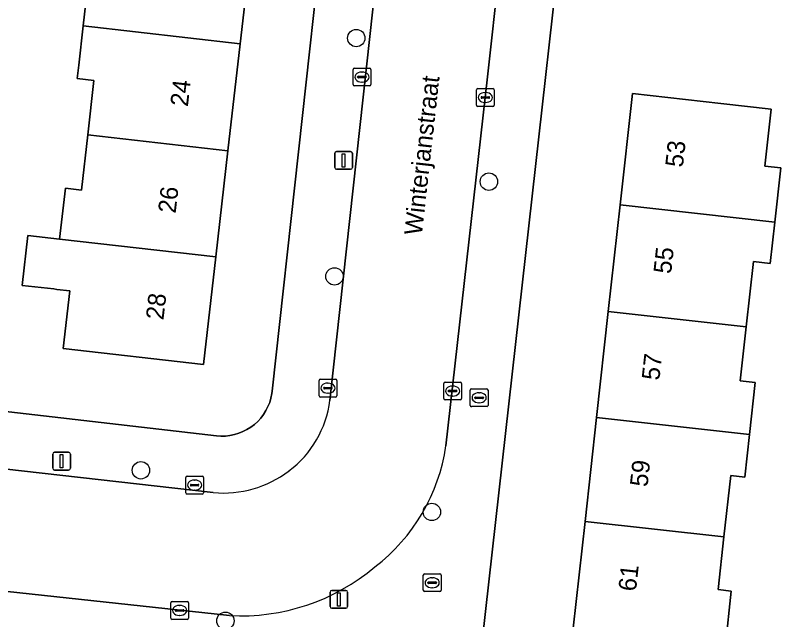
# Model space of a CAD drawing. Extents: x 162026 to 163502, y 387295 to 388169.
# Drawn here: x 162399.19 to 162442.26, y 387674.72 to 387708.7 of the extents above; entities that cross this region are included whole.
import ezdxf

# ---------------------------------------------------------------- set-up
doc = ezdxf.new("R2010")
doc.units = 0
for name, color, linetype in [('IMGEO_Boom', 7, 'Continuous'), ('IMGEO_Brandkraan', 7, 'Continuous'), ('IMGEO_Erf', 7, 'Continuous'), ('IMGEO_Kolk', 7, 'Continuous'), ('IMGEO_Lichtmast', 7, 'Continuous'), ('IMGEO_Openbare_ruimte_label', 7, 'Continuous'), ('IMGEO_Pand', 7, 'Continuous'), ('IMGEO_Pand_nummerreeks', 7, 'Continuous'), ('IMGEO_Rijbaan_lokaal_open', 7, 'Continuous'), ('IMGEO_Rioolput', 7, 'Continuous'), ('IMGEO_Voetpad_open', 7, 'Continuous')]:
    doc.layers.add(name, color=color, linetype=linetype)

msp = doc.modelspace()

# ---------------------------------------------------------------- linework, layer by layer
at = {"layer": 'IMGEO_Boom'}
for centre in [(162418.373, 387707.415), (162425.838, 387699.344), (162417.151, 387694.018), (162406.254, 387683.117), (162422.629, 387680.775), (162411.013, 387674.656)]:
    msp.add_circle(centre, 0.489, dxfattribs=at)
at = {"layer": 'IMGEO_Brandkraan'}
for p, q in [((162424.79, 387686.769), (162424.79, 387687.621)), ((162424.865, 387687.695), (162425.717, 387687.695)), ((162425.278, 387687.475), (162425.303, 387687.475)), ((162425.791, 387687.621), (162425.791, 387686.769)), ((162425.049, 387687.189), (162425.049, 387687.201)), ((162425.487, 387687.152), (162425.089, 387687.152)), ((162425.092, 387687.238), (162425.49, 387687.238)), ((162425.301, 387686.915), (162425.276, 387686.915)), ((162425.533, 387687.201), (162425.533, 387687.189)), ((162425.717, 387686.695), (162424.865, 387686.695))]:
    msp.add_line(p, q, dxfattribs=at)
for points in [[(162424.79, 387686.769), (162424.79, 387687.621)], [(162424.865, 387687.695), (162425.717, 387687.695)], [(162425.791, 387687.621), (162425.791, 387686.769)], [(162425.717, 387686.695), (162424.865, 387686.695)]]:
    msp.add_lwpolyline(points, dxfattribs=at)
for centre, radius, start, end in [((162424.867, 387687.619), 0.0765, 91.552, 178.448), ((162424.867, 387687.619), 0.0765, 91.552, 178.448), ((162425.715, 387687.619), 0.0765, 1.552, 88.448), ((162425.715, 387687.619), 0.0765, 1.552, 88.448), ((162425.089, 387687.198), 0.0403, 85.8775, 175.7526), ((162425.086, 387687.188), 0.0366, 178.938, 274.7102), ((162425.49, 387687.195), 0.043, 264.8664, 352.4533), ((162425.494, 387687.2), 0.0386, 1.7309, 96.639), ((162424.867, 387686.771), 0.0765, 181.552, 268.448), ((162424.867, 387686.771), 0.0765, 181.552, 268.448), ((162425.715, 387686.771), 0.0765, 271.552, 358.448), ((162425.715, 387686.771), 0.0765, 271.552, 358.448)]:
    msp.add_arc(centre, radius, start, end, dxfattribs=at)
for centre, major_axis, ratio, start_param, end_param in [((162425.277, 387687.195), (-0.387, 0.002), 0.722429, 4.712389, 7.853982), ((162425.302, 387687.195), (-0.39, 0.002), 0.717154, 1.570796, 4.712389)]:
    msp.add_ellipse(centre, major_axis=major_axis, ratio=ratio, start_param=start_param, end_param=end_param, dxfattribs=at)
at = {"layer": 'IMGEO_Erf'}
for points in [[(162433.651, 387750.442), (162432.585, 387742.149), (162433.168, 387742.074), (162425.088, 387670.179)], [(162390.537, 387687.351), (162410.507, 387685.056), (162410.761, 387685.039), (162411.015, 387685.045), (162411.268, 387685.074), (162411.517, 387685.125), (162411.761, 387685.198), (162411.997, 387685.292), (162412.223, 387685.408), (162412.439, 387685.543), (162412.641, 387685.697), (162412.829, 387685.868), (162413.001, 387686.055), (162413.156, 387686.257), (162413.292, 387686.472), (162413.408, 387686.699), (162413.503, 387686.934), (162413.577, 387687.178), (162413.629, 387687.427), (162413.649, 387687.57), (162418.095, 387727.958)], [(162412.529, 387713.102), (162411.84, 387707.09), (162411.151, 387701.077), (162410.467, 387695.109), (162409.775, 387689.069), (162401.884, 387689.973), (162402.255, 387693.207), (162401.523, 387693.291), (162401.357, 387693.31), (162399.573, 387693.515), (162399.894, 387696.322), (162401.679, 387696.117), (162402.007, 387698.976), (162402.91, 387698.873), (162403.266, 387701.981), (162403.616, 387705.035), (162402.67, 387705.144), (162402.757, 387705.902), (162403.009, 387708.103), (162403.313, 387710.755)], [(162430.585, 387674.243), (162431.25, 387680.243), (162431.898, 387686.091), (162432.557, 387692.036), (162433.221, 387698.036), (162433.915, 387704.295), (162438.885, 387703.744), (162441.722, 387703.429), (162441.366, 387700.218), (162442.261, 387700.119), (162441.924, 387697.072), (162441.666, 387694.743), (162440.726, 387694.847), (162440.319, 387691.175), (162439.983, 387688.144), (162440.831, 387688.05), (162440.508, 387685.137), (162440.243, 387682.739), (162439.449, 387682.827), (162439.067, 387679.377), (162438.738, 387676.41), (162439.482, 387676.327), (162439.146, 387673.294)]]:
    msp.add_lwpolyline(points, dxfattribs=at)
at = {"layer": 'IMGEO_Kolk'}
for p, q in [((162418.195, 387704.799), (162418.195, 387705.651)), ((162418.27, 387705.725), (162419.122, 387705.725)), ((162418.683, 387705.505), (162418.708, 387705.505)), ((162419.196, 387705.651), (162419.196, 387704.799)), ((162418.454, 387705.219), (162418.454, 387705.231)), ((162418.892, 387705.182), (162418.494, 387705.182)), ((162418.497, 387705.268), (162418.895, 387705.268)), ((162418.938, 387705.231), (162418.938, 387705.219)), ((162419.122, 387704.725), (162418.27, 387704.725)), ((162418.706, 387704.945), (162418.681, 387704.945)), ((162425.214, 387704.575), (162426.066, 387704.575)), ((162425.139, 387703.649), (162425.139, 387704.501)), ((162425.627, 387704.355), (162425.652, 387704.355)), ((162426.14, 387704.501), (162426.14, 387703.649)), ((162425.398, 387704.069), (162425.398, 387704.081)), ((162425.836, 387704.032), (162425.438, 387704.032)), ((162425.441, 387704.118), (162425.839, 387704.118)), ((162425.65, 387703.795), (162425.625, 387703.795)), ((162425.882, 387704.081), (162425.882, 387704.069)), ((162426.066, 387703.575), (162425.214, 387703.575)), ((162416.357, 387688.237), (162417.209, 387688.237)), ((162416.282, 387687.311), (162416.282, 387688.163)), ((162416.584, 387687.78), (162416.982, 387687.78)), ((162416.77, 387688.017), (162416.795, 387688.017)), ((162417.283, 387688.163), (162417.283, 387687.311)), ((162423.295, 387687.146), (162423.295, 387687.998)), ((162423.37, 387688.072), (162424.222, 387688.072)), ((162423.783, 387687.852), (162423.808, 387687.852)), ((162424.296, 387687.998), (162424.296, 387687.146)), ((162416.541, 387687.731), (162416.541, 387687.743)), ((162416.979, 387687.694), (162416.581, 387687.694)), ((162416.793, 387687.457), (162416.768, 387687.457)), ((162417.025, 387687.743), (162417.025, 387687.731)), ((162423.554, 387687.566), (162423.554, 387687.578)), ((162423.992, 387687.529), (162423.594, 387687.529)), ((162423.597, 387687.615), (162423.995, 387687.615)), ((162424.038, 387687.578), (162424.038, 387687.566)), ((162417.209, 387687.237), (162416.357, 387687.237)), ((162424.222, 387687.072), (162423.37, 387687.072)), ((162423.806, 387687.292), (162423.781, 387687.292)), ((162408.779, 387681.859), (162408.779, 387682.711)), ((162408.854, 387682.785), (162409.706, 387682.785)), ((162409.78, 387682.711), (162409.78, 387681.859)), ((162409.038, 387682.279), (162409.038, 387682.291)), ((162409.476, 387682.242), (162409.078, 387682.242)), ((162409.081, 387682.328), (162409.479, 387682.328)), ((162409.267, 387682.565), (162409.292, 387682.565)), ((162409.522, 387682.291), (162409.522, 387682.279)), ((162409.706, 387681.785), (162408.854, 387681.785)), ((162409.29, 387682.005), (162409.265, 387682.005)), ((162408.008, 387675.739), (162408.86, 387675.739)), ((162407.933, 387674.813), (162407.933, 387675.665)), ((162408.421, 387675.519), (162408.446, 387675.519)), ((162408.934, 387675.665), (162408.934, 387674.813)), ((162408.192, 387675.233), (162408.192, 387675.245)), ((162408.63, 387675.196), (162408.232, 387675.196)), ((162408.235, 387675.282), (162408.633, 387675.282)), ((162408.444, 387674.959), (162408.419, 387674.959)), ((162408.676, 387675.245), (162408.676, 387675.233)), ((162408.86, 387674.739), (162408.008, 387674.739))]:
    msp.add_line(p, q, dxfattribs=at)
for points in [[(162418.195, 387704.799), (162418.195, 387705.651)], [(162418.27, 387705.725), (162419.122, 387705.725)], [(162419.196, 387705.651), (162419.196, 387704.799)], [(162419.122, 387704.725), (162418.27, 387704.725)], [(162425.214, 387704.575), (162426.066, 387704.575)], [(162425.139, 387703.649), (162425.139, 387704.501)], [(162426.14, 387704.501), (162426.14, 387703.649)], [(162426.066, 387703.575), (162425.214, 387703.575)], [(162416.357, 387688.237), (162417.209, 387688.237)], [(162416.282, 387687.311), (162416.282, 387688.163)], [(162417.283, 387688.163), (162417.283, 387687.311)], [(162423.295, 387687.146), (162423.295, 387687.998)], [(162423.37, 387688.072), (162424.222, 387688.072)], [(162424.296, 387687.998), (162424.296, 387687.146)], [(162417.209, 387687.237), (162416.357, 387687.237)], [(162424.222, 387687.072), (162423.37, 387687.072)], [(162408.779, 387681.859), (162408.779, 387682.711)], [(162408.854, 387682.785), (162409.706, 387682.785)], [(162409.78, 387682.711), (162409.78, 387681.859)], [(162409.706, 387681.785), (162408.854, 387681.785)], [(162408.008, 387675.739), (162408.86, 387675.739)], [(162407.933, 387674.813), (162407.933, 387675.665)], [(162408.934, 387675.665), (162408.934, 387674.813)], [(162408.86, 387674.739), (162408.008, 387674.739)]]:
    msp.add_lwpolyline(points, dxfattribs=at)
for centre, radius, start, end in [((162418.272, 387705.649), 0.0765, 91.552, 178.448), ((162418.272, 387705.649), 0.0765, 91.552, 178.448), ((162419.12, 387705.649), 0.0765, 1.552, 88.448), ((162419.12, 387705.649), 0.0765, 1.552, 88.448), ((162418.494, 387705.228), 0.0403, 85.8775, 175.7526), ((162418.491, 387705.218), 0.0366, 178.938, 274.7102), ((162418.895, 387705.225), 0.043, 264.8664, 352.4533), ((162418.899, 387705.23), 0.0386, 1.7309, 96.639), ((162418.272, 387704.801), 0.0765, 181.552, 268.448), ((162418.272, 387704.801), 0.0765, 181.552, 268.448), ((162419.12, 387704.801), 0.0765, 271.552, 358.448), ((162419.12, 387704.801), 0.0765, 271.552, 358.448), ((162425.216, 387704.499), 0.0765, 91.552, 178.448), ((162425.216, 387704.499), 0.0765, 91.552, 178.448), ((162426.064, 387704.499), 0.0765, 1.552, 88.448), ((162426.064, 387704.499), 0.0765, 1.552, 88.448), ((162425.438, 387704.078), 0.0403, 85.8775, 175.7526), ((162425.435, 387704.068), 0.0366, 178.938, 274.7102), ((162425.839, 387704.075), 0.043, 264.8664, 352.4533), ((162425.843, 387704.08), 0.0386, 1.7309, 96.639), ((162425.216, 387703.651), 0.0765, 181.552, 268.448), ((162425.216, 387703.651), 0.0765, 181.552, 268.448), ((162426.064, 387703.651), 0.0765, 271.552, 358.448), ((162426.064, 387703.651), 0.0765, 271.552, 358.448), ((162416.359, 387688.161), 0.0765, 91.552, 178.448), ((162416.359, 387688.161), 0.0765, 91.552, 178.448), ((162417.207, 387688.161), 0.0765, 1.552, 88.448), ((162417.207, 387688.161), 0.0765, 1.552, 88.448), ((162416.581, 387687.74), 0.0403, 85.8775, 175.7526), ((162416.986, 387687.742), 0.0386, 1.7309, 96.639), ((162423.372, 387687.996), 0.0765, 91.552, 178.448), ((162423.372, 387687.996), 0.0765, 91.552, 178.448), ((162424.22, 387687.996), 0.0765, 1.552, 88.448), ((162424.22, 387687.996), 0.0765, 1.552, 88.448), ((162416.578, 387687.73), 0.0366, 178.938, 274.7102), ((162416.982, 387687.737), 0.043, 264.8664, 352.4533), ((162423.594, 387687.575), 0.0403, 85.8775, 175.7526), ((162423.591, 387687.565), 0.0366, 178.938, 274.7102), ((162423.995, 387687.572), 0.043, 264.8664, 352.4533), ((162423.999, 387687.577), 0.0386, 1.7309, 96.639), ((162416.359, 387687.313), 0.0765, 181.552, 268.448), ((162416.359, 387687.313), 0.0765, 181.552, 268.448), ((162417.207, 387687.313), 0.0765, 271.552, 358.448), ((162417.207, 387687.313), 0.0765, 271.552, 358.448), ((162423.372, 387687.148), 0.0765, 181.552, 268.448), ((162423.372, 387687.148), 0.0765, 181.552, 268.448), ((162424.22, 387687.148), 0.0765, 271.552, 358.448), ((162424.22, 387687.148), 0.0765, 271.552, 358.448), ((162408.856, 387682.709), 0.0765, 91.552, 178.448), ((162408.856, 387682.709), 0.0765, 91.552, 178.448), ((162409.704, 387682.709), 0.0765, 1.552, 88.448), ((162409.704, 387682.709), 0.0765, 1.552, 88.448), ((162409.078, 387682.288), 0.0403, 85.8775, 175.7526), ((162409.075, 387682.278), 0.0366, 178.938, 274.7102), ((162409.479, 387682.285), 0.043, 264.8664, 352.4533), ((162409.483, 387682.29), 0.0386, 1.7309, 96.639), ((162408.856, 387681.861), 0.0765, 181.552, 268.448), ((162408.856, 387681.861), 0.0765, 181.552, 268.448), ((162409.704, 387681.861), 0.0765, 271.552, 358.448), ((162409.704, 387681.861), 0.0765, 271.552, 358.448), ((162408.01, 387675.663), 0.0765, 91.552, 178.448), ((162408.01, 387675.663), 0.0765, 91.552, 178.448), ((162408.858, 387675.663), 0.0765, 1.552, 88.448), ((162408.858, 387675.663), 0.0765, 1.552, 88.448), ((162408.232, 387675.242), 0.0403, 85.8775, 175.7526), ((162408.229, 387675.232), 0.0366, 178.938, 274.7102), ((162408.633, 387675.239), 0.043, 264.8664, 352.4533), ((162408.637, 387675.244), 0.0386, 1.7309, 96.639), ((162408.01, 387674.815), 0.0765, 181.552, 268.448), ((162408.01, 387674.815), 0.0765, 181.552, 268.448), ((162408.858, 387674.815), 0.0765, 271.552, 358.448), ((162408.858, 387674.815), 0.0765, 271.552, 358.448)]:
    msp.add_arc(centre, radius, start, end, dxfattribs=at)
for centre, major_axis, ratio, start_param, end_param in [((162418.682, 387705.225), (-0.387, 0.002), 0.722429, 4.712389, 7.853982), ((162418.707, 387705.225), (-0.39, 0.002), 0.717154, 1.570796, 4.712389), ((162425.626, 387704.075), (-0.387, 0.002), 0.722429, 4.712389, 7.853982), ((162425.651, 387704.075), (-0.39, 0.002), 0.717154, 1.570796, 4.712389), ((162416.769, 387687.737), (-0.387, 0.002), 0.722429, 4.712389, 7.853982), ((162416.794, 387687.737), (-0.39, 0.002), 0.717154, 1.570796, 4.712389), ((162423.782, 387687.572), (-0.387, 0.002), 0.722429, 4.712389, 7.853982), ((162423.807, 387687.572), (-0.39, 0.002), 0.717154, 1.570796, 4.712389), ((162409.266, 387682.285), (-0.387, 0.002), 0.722429, 4.712389, 7.853982), ((162409.291, 387682.285), (-0.39, 0.002), 0.717154, 1.570796, 4.712389), ((162408.42, 387675.239), (-0.387, 0.002), 0.722429, 4.712389, 7.853982), ((162408.445, 387675.239), (-0.39, 0.002), 0.717154, 1.570796, 4.712389)]:
    msp.add_ellipse(centre, major_axis=major_axis, ratio=ratio, start_param=start_param, end_param=end_param, dxfattribs=at)
at = {"layer": 'IMGEO_Lichtmast'}
for p, q in [((162417.166, 387700.141), (162417.166, 387700.941)), ((162417.166, 387700.941), (162417.166, 387700.141)), ((162417.266, 387701.041), (162418.056, 387701.041)), ((162418.056, 387701.041), (162417.266, 387701.041)), ((162418.156, 387700.941), (162418.156, 387700.141)), ((162418.156, 387700.141), (162418.156, 387700.941)), ((162418.056, 387700.041), (162417.266, 387700.041)), ((162417.266, 387700.041), (162418.056, 387700.041)), ((162401.295, 387683.233), (162401.295, 387684.033)), ((162401.295, 387684.033), (162401.295, 387683.233)), ((162401.395, 387684.133), (162402.185, 387684.133)), ((162402.185, 387684.133), (162401.395, 387684.133)), ((162402.285, 387684.033), (162402.285, 387683.233)), ((162402.285, 387683.233), (162402.285, 387684.033)), ((162402.185, 387683.133), (162401.395, 387683.133)), ((162401.395, 387683.133), (162402.185, 387683.133)), ((162416.9, 387675.462), (162416.9, 387676.262)), ((162416.9, 387676.262), (162416.9, 387675.462)), ((162417, 387676.362), (162417.79, 387676.362)), ((162417.79, 387676.362), (162417, 387676.362)), ((162417.89, 387676.262), (162417.89, 387675.462)), ((162417.89, 387675.462), (162417.89, 387676.262)), ((162417.79, 387675.362), (162417, 387675.362)), ((162417, 387675.362), (162417.79, 387675.362))]:
    msp.add_line(p, q, dxfattribs=at)
for points in [[(162417.586, 387700.916), (162417.736, 387700.916), (162417.736, 387700.166), (162417.586, 387700.166), (162417.586, 387700.916)], [(162401.715, 387684.008), (162401.865, 387684.008), (162401.865, 387683.258), (162401.715, 387683.258), (162401.715, 387684.008)], [(162417.32, 387676.237), (162417.47, 387676.237), (162417.47, 387675.487), (162417.32, 387675.487), (162417.32, 387676.237)]]:
    msp.add_lwpolyline(points, dxfattribs=at)
for centre, start, end in [((162417.266, 387700.941), 90, 180), ((162417.266, 387700.941), 90, 180), ((162418.056, 387700.941), 0, 90), ((162418.056, 387700.941), 360, 90), ((162417.266, 387700.141), 180, 270), ((162417.266, 387700.141), 180, 270), ((162418.056, 387700.141), 270, 0), ((162418.056, 387700.141), 270, 0), ((162401.395, 387684.033), 90, 180), ((162401.395, 387684.033), 90, 180), ((162402.185, 387684.033), 0, 90), ((162402.185, 387684.033), 360, 90), ((162401.395, 387683.233), 180, 270), ((162401.395, 387683.233), 180, 270), ((162402.185, 387683.233), 270, 0), ((162402.185, 387683.233), 270, 0), ((162417, 387676.262), 90, 180), ((162417, 387676.262), 90, 180), ((162417.79, 387676.262), 0, 90), ((162417.79, 387676.262), 360, 90), ((162417, 387675.462), 180, 270), ((162417, 387675.462), 180, 270), ((162417.79, 387675.462), 270, 0), ((162417.79, 387675.462), 270, 0)]:
    msp.add_arc(centre, 0.1, start, end, dxfattribs=at)
at = {"layer": 'IMGEO_Pand'}
for points in [[(162411.84, 387707.09), (162412.529, 387713.102), (162404.688, 387714.001), (162404.303, 387710.641), (162403.313, 387710.755), (162403.009, 387708.103)], [(162411.151, 387701.077), (162411.84, 387707.09), (162403.009, 387708.103), (162402.757, 387705.902), (162402.67, 387705.144), (162403.616, 387705.035), (162403.266, 387701.981)], [(162441.924, 387697.072), (162442.261, 387700.119), (162441.366, 387700.218), (162441.722, 387703.429), (162438.885, 387703.744), (162433.915, 387704.295), (162433.221, 387698.036)], [(162403.266, 387701.981), (162402.91, 387698.873), (162402.007, 387698.976), (162401.679, 387696.117), (162410.467, 387695.109), (162411.151, 387701.077)], [(162433.221, 387698.036), (162432.557, 387692.036), (162440.319, 387691.175), (162440.726, 387694.847), (162441.666, 387694.743), (162441.924, 387697.072)], [(162410.467, 387695.109), (162401.679, 387696.117), (162399.894, 387696.322), (162399.573, 387693.515), (162401.357, 387693.31), (162401.523, 387693.291), (162402.255, 387693.207), (162401.884, 387689.973), (162409.775, 387689.069)], [(162440.508, 387685.137), (162440.831, 387688.05), (162439.983, 387688.144), (162440.319, 387691.175), (162432.557, 387692.036), (162431.898, 387686.091)], [(162431.898, 387686.091), (162431.25, 387680.243), (162439.067, 387679.377), (162439.449, 387682.827), (162440.243, 387682.739), (162440.508, 387685.137)], [(162431.25, 387680.243), (162430.585, 387674.243), (162439.146, 387673.294), (162439.482, 387676.327), (162438.738, 387676.41), (162439.067, 387679.377)]]:
    msp.add_lwpolyline(points, close=True, dxfattribs=at)
at = {"layer": 'IMGEO_Rijbaan_lokaal_open'}
for points in [[(162421.368, 387727.812), (162416.894, 387687.047)], [(162423.42, 387684.486), (162425.761, 387705.232), (162426.424, 387711.183), (162428.221, 387727.308)], [(162410.331, 387681.861), (162393.205, 387683.797), (162388.435, 387684.336), (162387.668, 387677.512), (162392.308, 387677.004), (162411.245, 387674.951)]]:
    msp.add_lwpolyline(points, dxfattribs=at)
for centre, radius, start, end in [((162411.008, 387687.813), 5.935, 307.1181, 352.5865), ((162413.025, 387686.018), 10.508, 307.5393, 351.6173), ((162410.877, 387688.005), 6.168, 264.9255, 307.0186), ((162411.874, 387686.676), 11.742, 266.9304, 310.0361)]:
    msp.add_arc(centre, radius, start, end, dxfattribs=at)
at = {"layer": 'IMGEO_Rioolput'}
for p, q in [((162422.148, 387676.37), (162422.148, 387677.222)), ((162422.223, 387677.296), (162423.075, 387677.296)), ((162422.636, 387677.076), (162422.661, 387677.076)), ((162423.149, 387677.222), (162423.149, 387676.37)), ((162422.407, 387676.79), (162422.407, 387676.802)), ((162422.845, 387676.753), (162422.447, 387676.753)), ((162422.45, 387676.839), (162422.848, 387676.839)), ((162422.891, 387676.802), (162422.891, 387676.79)), ((162423.075, 387676.296), (162422.223, 387676.296)), ((162422.659, 387676.516), (162422.634, 387676.516))]:
    msp.add_line(p, q, dxfattribs=at)
for points in [[(162422.148, 387676.37), (162422.148, 387677.222)], [(162422.223, 387677.296), (162423.075, 387677.296)], [(162423.149, 387677.222), (162423.149, 387676.37)], [(162423.075, 387676.296), (162422.223, 387676.296)]]:
    msp.add_lwpolyline(points, dxfattribs=at)
for centre, radius, start, end in [((162422.225, 387677.22), 0.0765, 91.552, 178.448), ((162422.225, 387677.22), 0.0765, 91.552, 178.448), ((162423.073, 387677.22), 0.0765, 1.552, 88.448), ((162423.073, 387677.22), 0.0765, 1.552, 88.448), ((162422.447, 387676.799), 0.0403, 85.8775, 175.7526), ((162422.444, 387676.789), 0.0366, 178.938, 274.7102), ((162422.848, 387676.796), 0.043, 264.8664, 352.4533), ((162422.852, 387676.801), 0.0386, 1.7309, 96.639), ((162422.225, 387676.372), 0.0765, 181.552, 268.448), ((162422.225, 387676.372), 0.0765, 181.552, 268.448), ((162423.073, 387676.372), 0.0765, 271.552, 358.448), ((162423.073, 387676.372), 0.0765, 271.552, 358.448)]:
    msp.add_arc(centre, radius, start, end, dxfattribs=at)
for centre, major_axis, ratio, start_param, end_param in [((162422.635, 387676.796), (-0.387, 0.002), 0.722429, 4.712389, 7.853982), ((162422.66, 387676.796), (-0.39, 0.002), 0.717154, 1.570796, 4.712389)]:
    msp.add_ellipse(centre, major_axis=major_axis, ratio=ratio, start_param=start_param, end_param=end_param, dxfattribs=at)
at = {"layer": 'IMGEO_Voetpad_open'}
for points in [[(162354.825, 387677.763), (162355.06, 387677.88), (162355.305, 387677.976), (162355.557, 387678.05), (162355.815, 387678.1), (162356.076, 387678.128), (162356.339, 387678.132), (162356.601, 387678.112), (162386.507, 387674.529), (162391.724, 387673.904), (162393.448, 387673.699), (162419.619, 387670.747), (162425.088, 387670.179), (162433.168, 387742.074), (162432.585, 387742.149), (162431.245, 387742.321), (162427.027, 387742.863), (162362.56, 387750)], [(162418.095, 387727.958), (162413.649, 387687.57), (162413.629, 387687.427), (162413.577, 387687.178), (162413.503, 387686.934), (162413.408, 387686.699), (162413.292, 387686.472), (162413.156, 387686.257), (162413.001, 387686.055), (162412.829, 387685.868), (162412.641, 387685.697), (162412.439, 387685.543), (162412.223, 387685.408), (162411.997, 387685.292), (162411.761, 387685.198), (162411.517, 387685.125), (162411.268, 387685.074), (162411.015, 387685.045), (162410.761, 387685.039), (162410.507, 387685.056), (162390.537, 387687.351)], [(162416.894, 387687.047), (162421.368, 387727.812)], [(162428.221, 387727.308), (162426.424, 387711.183), (162425.761, 387705.232), (162423.42, 387684.486)], [(162393.205, 387683.797), (162410.331, 387681.861)], [(162411.245, 387674.951), (162392.308, 387677.004), (162387.668, 387677.512), (162379.974, 387678.355), (162373.999, 387679.009), (162369.61, 387679.49), (162362.969, 387680.217), (162355.844, 387680.998), (162355.405, 387681.025), (162354.965, 387681.013)]]:
    msp.add_lwpolyline(points, dxfattribs=at)
for centre, radius, start, end in [((162411.008, 387687.813), 5.935, 307.1181, 352.5865), ((162413.025, 387686.018), 10.508, 307.5393, 351.6173), ((162410.877, 387688.005), 6.168, 264.9255, 307.0186), ((162411.874, 387686.676), 11.742, 266.9304, 310.0361)]:
    msp.add_arc(centre, radius, start, end, dxfattribs=at)

# ---------------------------------------------------------------- texts
at = {"layer": 'IMGEO_Openbare_ruimte_label'}
msp.add_text('Winterjanstraat', height=1, rotation=83.6282, dxfattribs=at).set_placement((162422.065, 387696.298))
at = {"layer": 'IMGEO_Pand_nummerreeks'}
for s, rotation, p in [('24', 83.4618, (162408.896, 387703.533)), ('53', 83.6766, (162436.753, 387700.119)), ('26', 83.4618, (162408.208, 387697.534)), ('55', 83.6766, (162436.089, 387694.131)), ('28', 83.4628, (162407.522, 387691.538)), ('57', 83.6766, (162435.426, 387688.144)), ('59', 83.6766, (162434.762, 387682.156)), ('61', 83.6766, (162434.112, 387676.281))]:
    msp.add_text(s, height=1, rotation=rotation, dxfattribs=at).set_placement(p)

doc.saveas('drawing.dxf')
